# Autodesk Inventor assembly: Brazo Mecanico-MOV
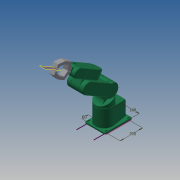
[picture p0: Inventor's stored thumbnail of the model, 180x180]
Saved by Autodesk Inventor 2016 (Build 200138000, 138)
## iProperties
Created: 2012-05
Part Number: Brazo Mecanico-MOV
Document SubType Name: Assembly
Designer: julian.chica
Mass: 1751.01 g
Surface Area: 13798 cm^2
Volume: 1751.01 cm^3
Density: 1 g/cm^3
Author: julian.chica
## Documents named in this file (8)
- C:\Test ExamProfessor 2015\Brazo Mecanico-MOV.iam
- C:\Test ExamProfessor 2015\Inventor Básico 2012 - DATASET\06 ENSAMBLE\Robot-Base-Model-A.ipt
- C:\Test ExamProfessor 2015\Inventor Básico 2012 - DATASET\06 ENSAMBLE\Robot-Axis1-2.ipt
- C:\Test ExamProfessor 2015\Inventor Básico 2012 - DATASET\06 ENSAMBLE\Robot-Axis2-3.ipt
- C:\Test ExamProfessor 2015\Inventor Básico 2012 - DATASET\06 ENSAMBLE\Robot-Axis3-4.ipt
- C:\Test ExamProfessor 2015\Inventor Básico 2012 - DATASET\06 ENSAMBLE\Robot-Axis4-5.ipt
- C:\Test ExamProfessor 2015\Inventor Básico 2012 - DATASET\06 ENSAMBLE\Robot-Axis5.ipt
- C:\Test ExamProfessor 2015\Inventor Básico 2012 - DATASET\06 ENSAMBLE\TENAZA.ipt
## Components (7 placed, 7 different names)
1. Robot-Base-Model-A:1 — Insert:1, Angle:1
2. Robot-Axis1-2:1 — Insert:1, Angle:1, Insert:2, Angle:2
3. Robot-Axis2-3:1 — Insert:2, Angle:2, Insert:3, Angle:3
4. Robot-Axis3-4:1 — Insert:3, Angle:3, Insert:4, Angle:4
5. Robot-Axis4-5:1 — Insert:4, Angle:4, Insert:5, Angle:6
6. Robot-Axis5:1 — Insert:5, Mate:1, Mate:2, Angle:5, Angle:6
7. TENAZA:1 — Mate:1, Mate:2, Angle:5
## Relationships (13: Angle 6, Insert 5, Mate 2)
- Insert:1: Robot-Base-Model-A:1 ↔ Robot-Axis1-2:1
- Angle:1: Robot-Base-Model-A:1 ↔ Robot-Axis1-2:1
- Insert:2: Robot-Axis1-2:1 ↔ Robot-Axis2-3:1
- Angle:2: Robot-Axis1-2:1 ↔ Robot-Axis2-3:1
- Insert:3: Robot-Axis2-3:1 ↔ Robot-Axis3-4:1
- Angle:3: Robot-Axis2-3:1 ↔ Robot-Axis3-4:1
- Insert:4: Robot-Axis3-4:1 ↔ Robot-Axis4-5:1
- Angle:4: Robot-Axis3-4:1 ↔ Robot-Axis4-5:1
- Insert:5: Robot-Axis4-5:1 ↔ Robot-Axis5:1
- Mate:1: Robot-Axis5:1 ↔ TENAZA:1
- Mate:2: Robot-Axis5:1 ↔ TENAZA:1
- Angle:5: Robot-Axis5:1 ↔ TENAZA:1
- Angle:6: Robot-Axis4-5:1 ↔ Robot-Axis5:1
